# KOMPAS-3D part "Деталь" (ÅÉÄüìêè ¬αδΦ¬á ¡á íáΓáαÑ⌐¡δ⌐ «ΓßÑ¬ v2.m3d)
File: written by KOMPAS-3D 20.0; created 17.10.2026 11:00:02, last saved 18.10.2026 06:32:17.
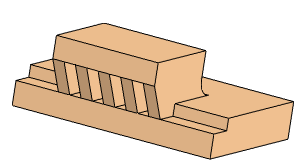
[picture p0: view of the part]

Document properties: Полное имя файла: D:\myProjects\Progect_esp32\box_compas\корпус\ПРОБНИК крышка на батарейный отсек v2.m3d

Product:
- Part/product: Деталь
    Масса: 0.00338996
  - Body: Тело 5
      Масса: 0.0737567
  - Body: Тело 2
      Масса: 0.0737567
  - Body: Тело 1
      Масса: 0.0737567

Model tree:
1. Эскиз:1
2. Элемент выдавливания:1
     Расстояние 1 = 0.8
3. Эскиз:2  (with: Элемент выдавливания:1)
4. Элемент выдавливания:2
     Расстояние 1 = 1.6
5. Эскиз:5  (with: Элемент выдавливания:2)
6. Элемент выдавливания:6
     Расстояние 2 = 1.6
7. Эскиз:6  (with: Элемент выдавливания:2, Элемент выдавливания:1)
8. Элемент выдавливания:7
     Расстояние 2 = 1
9. Массив по сетке:2  (with: Элемент выдавливания:7, Эскиз:6)  (4 pattern instances)
     Шаг 1 = 83.2; Угол раствора = -90; Шаг 2 = 36.8
10. Скругление:1  (with: Элемент выдавливания:2)
     Радиус = 4
11. Эскиз:8  (with: Элемент выдавливания:2)
12. Элемент выдавливания:8
     Расстояние 2 = 2.4
13. Смещенная плоскость:1  (with: Элемент выдавливания:2)
     Расстояние = -45
14. Зеркальный массив:1
15. Экземпляр ( 1 )
16. Экземпляр ( 2 )  (with: Элемент выдавливания:8)
17. Эскиз:10  (with: Элемент выдавливания:1)
18. Элемент выдавливания:9
     Расстояние 1 = 1.5
19. Эскиз:11  (with: Элемент выдавливания:9)
20. Элемент выдавливания:10
     Расстояние 1 = 1.5
21. Скругление:4  (with: Элемент выдавливания:10)
     Радиус = 1
22. Эскиз:15  (with: Элемент выдавливания:9, Элемент выдавливания:10, Скругление:4, Элемент выдавливания:1)
23. Эскиз:16  (with: Элемент выдавливания:9, Элемент выдавливания:10, Скругление:4, Элемент выдавливания:1)
24. Элемент выдавливания:13
     Расстояние 2 = 0.8
25. Скругление:6  (with: Элемент выдавливания:9)
     Радиус = 1
26. Элемент выдавливания:14
     Расстояние 2 = 0.8
27. Массив по сетке:5  (with: Элемент выдавливания:14, Элемент выдавливания:10)  (5 pattern instances)
     Шаг 1 = 1.6; Угол раствора = 90
28. Скругление:7  (with: Элемент выдавливания:9)
     Радиус = 1.2
29. Массив по сетке:6  (with: Элемент выдавливания:13, Элемент выдавливания:1)  (5 pattern instances)
     Шаг 1 = 1.6; Угол раствора = 90
30. Эскиз:20  (with: Элемент выдавливания:2, Элемент выдавливания:6, Скругление:1, Элемент выдавливания:8)
31. Элемент выдавливания:17
     Расстояние 2 = 5.4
